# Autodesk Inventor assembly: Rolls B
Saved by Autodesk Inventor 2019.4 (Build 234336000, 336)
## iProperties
Created: 2020-05
Part Number: Rolls B
Document SubType Name: Assembly
Designer: Administrator
Title: Rolls B
Author: Administrator
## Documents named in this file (3)
- c:\worker\convert-fusion-r04\tmp\job-1\2948\output\files\178587fc-8fac-4631-8e4c-cfe484ac4050\Rolls B.iam
- c:\worker\convert-fusion-r04\tmp\job-1\2948\output\files\178587fc-8fac-4631-8e4c-cfe484ac4050\Component15.ipt
- c:\worker\convert-fusion-r04\tmp\job-1\2948\output\files\178587fc-8fac-4631-8e4c-cfe484ac4050\Rolls B.ipt
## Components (2 placed, 2 different names)
1. Component15:1
2. Rolls B
